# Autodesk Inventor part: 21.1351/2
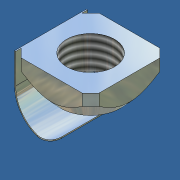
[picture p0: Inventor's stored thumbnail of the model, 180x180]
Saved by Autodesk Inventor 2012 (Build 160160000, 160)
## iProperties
Created: 2006-12
Part Number: 21.1351/2
Document SubType Name: Modeling
Designer: Andy Moles
Material: Steel, Mild
Density: 7.86 g/cm^3
Mass: 4.25424 g
Surface Area: 8.34272 cm^2
Volume: 0.541252 cm^3
Description: M8 SQUARE NUT POS FXG
Vendor: S
Title: M8 SQUARE NUT POS FXG
Author: Andy Moles
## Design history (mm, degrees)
sketch "Sketch2"
  geometry: L1 (-5.086, -6.5)-(5.086, -6.5); L2 (6.5, -5.086)-(6.5, 5.086); L3 (5.086, 6.5)-(-5.086, 6.5); L4 (-6.5, 5.086)-(-6.5, -5.086); L5 (-6.5, 6.5)-(6.5, -6.5); L6 (5.086, 6.5)-(6.5, 5.086); L7 (0, -6.5)-(0, 6.5); L8 (-6.5, 0)-(6.5, 0); L9 (-5.086, 6.5)-(-6.5, 5.086); L10 (-5.086, -6.5)-(-6.5, -5.086); L11 (5.086, -6.5)-(6.5, -5.086); C1 r 4 at (0, 0); 2 further points
  constraints: 22 end point, 6 symmetric about line, 4 parallel, 3 midpoint, 2 coincident, 2 perpendicular, 1 centre point, 1 horizontal
  dimensions: "THREAD" = 8 diameter of C1; "d3" = 45 deg angle of L3 L6 (derived); "d4" = 2 distance of L3.start L2.end
extrude "Extrusion1" new body sketch "Sketch2" distance "d5" = 5.5; taper "d6" = 0 deg
workplane "Work Plane1"
sketch "Sketch4"
  geometry: L1 (12.192, 0)-(4.192, 0) reference; L2 (8.192, 0)-(13.192, 0); L3 (16.385, 5.5)-(16.385, 3.5); L4 (13.192, 0)-(16.797, 3.952); L5 (13.192, 0)-(16.385, 0); L6 (16.385, 3.5)-(16.385, 0); L7 (16.797, 3.952)-(16.797, -0.412); L8 (16.797, -0.412)-(13.192, -0.412); L9 (13.192, -0.412)-(13.192, 0); L10 (8.192, 5.5)-(8.192, 0); L11 (16.385, 5.5)-(16.385, 0) reference; L12 (16.385, 3.5)-(17.502, 3.5); L13 (9.192, 5.5)-(16.385, 5.5) reference
  constraints: 20 end point, 6 perpendicular, 1 collinear, 1 midpoint, 1 parallel, 1 point on line
  dimensions: "d10" = 5 distance of L2.start L2.end; "d15" = 2 distance between parallel lines of L12 L13
revolve "Revolution1" sketch "Sketch4" stored, may be unused: angle "d12" = 90 deg
thread "Thread1" dims "d13" = 10, "d14" = 0
sketch "Sketch6"
  geometry: L1 (2.954, -2.535)-(2.954, 6.006); L2 (2.954, -2.535)-(2.954, -7.535); L3 (2.954, -2.535)-(3.154, -2.535); L4 (3.154, -2.535)-(3.154, -7.535); L5 (-2.646, -13.135)-(-2.646, -13.335); L6 (2.954, 0)-(2.954, -1.933); L7 (-8.632, -2.535)-(1.539, -2.535) reference; L8 (2.954, -2.535)-(2.954, -4.468) reference; A1 r 5.374 centre (-2.416, -7.766) between (-2.646, -13.135) and (2.954, -7.535); A2 r 5.574 centre (-2.416, -7.766) between (-2.646, -13.335) and (3.154, -7.535); 4 further points; 1 other entity
  constraints: 12 end point, 4 point on circle, 3 collinear, 2 centre point, 2 horizontal, 2 parallel, 2 perpendicular, 1 coincident, 3 other
  dimensions: "d25" = 5 distance of L1.start L2.end; "d23" = 0.2 distance of L1.start L3.end; "d22" = 0.2 distance of L5.start L5.end; "d21" = 10.8 distance from line of L5.end L3; "d24" = 5.37434 radius of A1
extrude "Extrusion3" join sketch "Sketch6" taper "d27" = 0 deg; stored distance "d28" = 12
fillet "Fillet2" dims "d29" = 2
body "Solid1"
